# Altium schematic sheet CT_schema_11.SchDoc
size 254 x 194 mm
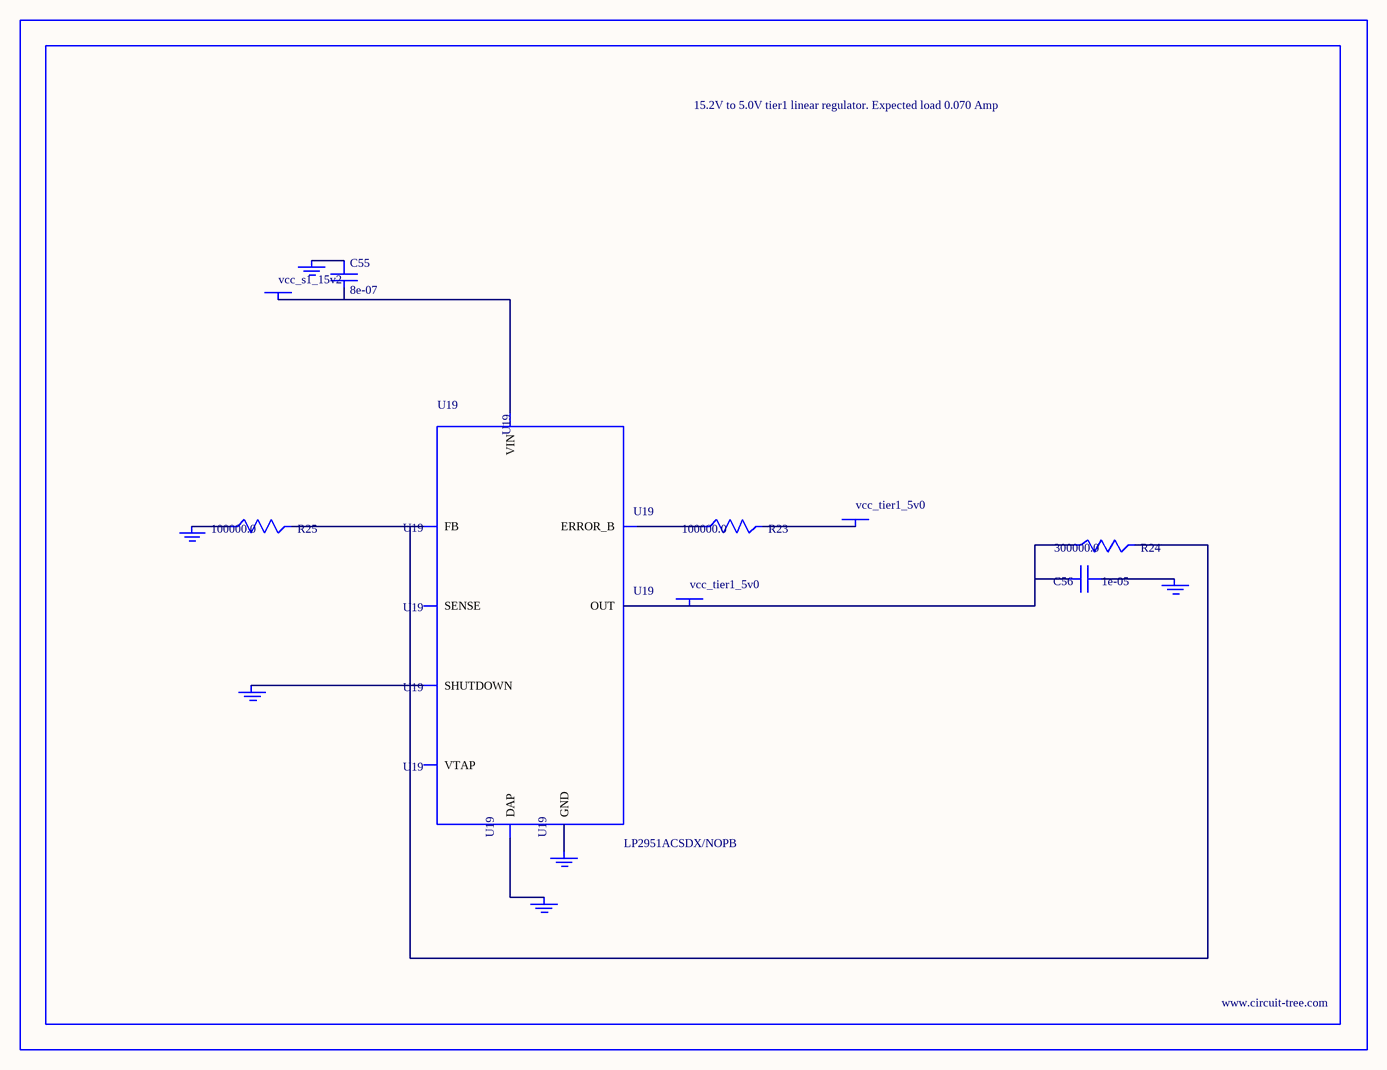
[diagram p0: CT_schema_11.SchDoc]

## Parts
BORDER10  (no value)
C55  8e-07  [R0603]
C56  1e-05  [C1210]
GND_INSTANCE_10_0  (no value)
GND_INSTANCE_10_1  (no value)
GND_INSTANCE_10_2  (no value)
GND_INSTANCE_10_3  (no value)
GND_INSTANCE_10_4  (no value)
GND_INSTANCE_10_5  (no value)
POWER_INSTANCE_10_0  vcc_tier1_5v0
POWER_INSTANCE_10_1  vcc_s1_15v2
POWER_INSTANCE_10_2  vcc_tier1_5v0
R23  100000.0  [R0603]
R24  300000.0  [R0603]
R25  100000.0  [R0603]
U19  LP2951ACSDX/NOPB  [WSON-8]

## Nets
NetC55_1: C55.1 GND_INSTANCE_10_3.0(GND)
NetC55_2: C55.2 POWER_INSTANCE_10_1.0(PWR) U19.8(VIN)
NetC56_1: C56.1 GND_INSTANCE_10_0.0(GND)
NetC56_2: C56.2 POWER_INSTANCE_10_2.0(PWR) R24.1 U19.1(OUT)
NetGND_INSTANCE_10_1_0: GND_INSTANCE_10_1.0(GND) U19.3(SHUTDOWN)
NetGND_INSTANCE_10_2_0: GND_INSTANCE_10_2.0(GND) R25.1
NetGND_INSTANCE_10_4_0: GND_INSTANCE_10_4.0(GND) U19.PAD(DAP)
NetGND_INSTANCE_10_5_0: GND_INSTANCE_10_5.0(GND) U19.4(GND)
NetPOWER_INSTANCE_10_0_0: POWER_INSTANCE_10_0.0(PWR) R23.2
NetR23_1: R23.1 U19.5(ERROR_B)
NetR24_2: R24.2 R25.2 U19.7(FB)

Not connected (* = marked no-connect by the designer): U19 2(SENSE) 6(VTAP)

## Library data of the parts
BORDER10 = BORDER_PAGE10
C55 = C55
C56 = GRM32DR61E106MA12L
GND_INSTANCE_10_0-GND_INSTANCE_10_5 = GND
POWER_INSTANCE_10_0-POWER_INSTANCE_10_2 = PWR
R23 R25 = RC0603JR-07100KL
R24 = RC0603JR-07300KL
